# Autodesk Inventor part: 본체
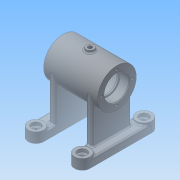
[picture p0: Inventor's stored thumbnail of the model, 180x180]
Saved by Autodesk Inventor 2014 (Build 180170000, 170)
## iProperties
Created: 2015-11
Part Number: 본체
Material: 알루미늄 6061
Document SubType Name: Modeling
Designer: net
Density: 2.71 g/cm^3
Appearance: 알루미늄 - 평지
Mass: 359.021 g
Surface Area: 459.454 cm^2
Volume: 132.48 cm^3
Author: net
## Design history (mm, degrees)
sketch "스케치1"
  geometry: C1 r 25 at (0, 0); 1 further point
  constraints: 1 centre point, 1 coincident
  dimensions: "d0" = 50 diameter of C1
extrude "돌출1" new body sketch "스케치1" distance "d1" = 70; taper "d2" = 0 deg
sketch "스케치2"
  geometry: C1 r 25 at (0, 0) reference; C2 r 16 at (0, 0)
  constraints: 1 centre point, 1 coincident
  dimensions: "d3" = 32 diameter of C2
extrude "돌출2" cut sketch "스케치2" distance "d4" = 12; taper "d5" = 0 deg
sketch "스케치3"
  geometry: C1 r 16 at (0, 0) reference; C2 r 14 at (0, 0)
  constraints: 1 centre point, 1 coincident
  dimensions: "d6" = 28 diameter of C2
extrude "돌출3" cut sketch "스케치3" distance "d7" = 2; taper "d8" = 0 deg
sketch "스케치4"
  geometry: C1 r 14 at (0, 0) reference; C2 r 21 at (0, 0)
  constraints: 1 centre point, 1 coincident
  dimensions: "d9" = 42 diameter of C2
extrude "돌출4" cut sketch "스케치4" distance "d10" = 42; taper "d11" = 0 deg
sketch "스케치5"
  geometry: C1 r 21 at (0, 0) reference; C2 r 14 at (0, 0)
  constraints: 1 centre point, 1 coincident
  dimensions: "d12" = 28 diameter of C2
extrude "돌출5" cut sketch "스케치5" distance "d13" = 2; taper "d14" = 0 deg
sketch "스케치6"
  geometry: C1 r 25 at (0, 0) reference; C2 r 16 at (0, 0)
  constraints: 1 centre point, 1 coincident
  dimensions: "d15" = 32 diameter of C2
extrude "돌출6" cut sketch "스케치6" distance "d16" = 12; taper "d17" = 0 deg
fillet "모깎기1" dims "d18" = 0.3
chamfer "모따기1" distance "d19" = 1; stored, may be unused: second distance "d20" = 2, angle "d21" = 45 deg
node "작업 평면2"
  node "작업 평면1"
sketch "스케치7"
  geometry: L1 (-25, 0)-(25, 0) reference; C1 r 5 at (0, 35); 1 further point
  constraints: 1 centre point
  dimensions: "d23" = 10 diameter of C1; "d24" = 35 distance from line of L1 C1.centre
extrude "돌출7" join sketch "스케치7" stored distance "d25" = 12; taper "d26" = 0 deg
fillet "모깎기2" dims "d27" = 2
sketch "스케치8"
  geometry: C1 r 5 at (0, 0) reference; 1 further point
hole "구멍1" sketch "스케치8" at (0, 0) diameter "d28" = 5.188; stored, may be unused: countersink angle "d32" = 90 deg, drill point angle "d34" = 118 deg; dims "d29" = 8, "d30" = 4, "d31" = 2, "d33" = 8
fillet "모깎기3" dims "d35" = 3
sketch "스케치9"
  geometry: C1 r 17 at (0, 0) reference; A1 r 20 centre (0, 0) between (0, 20) and (20, 0); 2 further points
  constraints: 4 point on circle, 1 centre point, 1 coincident
  dimensions: "d36" = 40 diameter of A1
hole "구멍2" sketch "스케치9" at (0, 20), (20, 0), (0, -20), (-20, 0) diameter "d37" = 3.242; stored, may be unused: countersink angle "d41" = 90 deg, drill point angle "d43" = 118 deg; dims "d38" = 8, "d39" = 4, "d40" = 2, "d42" = 10
sketch "스케치10"
  geometry: C1 r 17 at (0, 0) reference; A1 r 20 centre (0, 0) between (0, 20) and (20, 0); 2 further points
  constraints: 4 point on circle, 1 centre point, 1 coincident
  dimensions: "d44" = 40 diameter of A1
hole "구멍3" sketch "스케치10" at (0, 20), (20, 0), (0, -20), (-20, 0) diameter "d45" = 3.242; stored, may be unused: countersink angle "d49" = 90 deg, drill point angle "d51" = 118 deg; dims "d46" = 8, "d47" = 4, "d48" = 2, "d50" = 10
node "작업 평면4"
sketch "스케치11"
  geometry: L1 (0, 0)-(0, -25); L2 (0, 0)-(12.5, -21.651); L3 (12.5, -21.651)-(14, -24.249); L4 (14, -24.249)-(19.196, -21.249); L5 (19.196, -21.249)-(17.331, -18.018); A1 r 25 centre (0, 0) between (0, -25) and (12.5, -21.651) reference; 1 further point
  constraints: 10 end point, 3 point on circle, 2 perpendicular, 1 collinear, 1 vertical
  dimensions: "d53" = 30 deg angle of L2 L1; "d54" = 12 diameter of L4.end L3; "d55" = 28 distance from line of L4 point (0, 0)
revolve "회전1" sketch "스케치11" stored, may be unused: angle "d56" = 90 deg
sketch "스케치12"
  geometry: C1 r 6 at (0, 0) reference; 1 further point
hole "구멍4" sketch "스케치12" at (0, 0) diameter "d57" = 5.188; stored, may be unused: countersink angle "d61" = 90 deg, drill point angle "d63" = 118 deg; dims "d58" = 8, "d59" = 4, "d60" = 2, "d62" = 10
node "작업 평면5"
node "작업 평면6"
node "작업 평면7"
node "작업 평면8"
sketch "스케치15"
  geometry: L1 (-25, 0)-(-25, 70) reference; L2 (-25, 35)-(-17.013, 35); L3 (25, 70)-(-25, 70) reference; L4 (0, 70)-(0, 56.054); C1 r 10 at (40, 65); C2 r 10 at (-40, 65); 1 further point
  constraints: 4 end point, 2 centre point, 2 midpoint, 2 perpendicular, 1 symmetric about line, 1 other
  dimensions: "d81" = 20 diameter of C1; "d93" = 80 distance of C1.centre C2.centre; "d94" = 30 vertical distance of L2.end C2.centre
extrude "돌출10" join sketch "스케치15" distance "d89" = 13; taper "d90" = 0 deg
sketch "스케치16"
  geometry: L1 (-80, 10)-(0, 10); L2 (-80, -10)-(0, -10); A1 r 10 centre (0, 0) between (0, 10) and (0, -10) reference; A2 r 10 centre (-80, 0) between (-80, 10) and (-80, -10) reference; 1 further point
  constraints: 4 end point, 4 point on circle, 4 tangent
extrude "돌출11" join sketch "스케치16" distance "d91" = 10; taper "d92" = 0 deg
node "작업 평면9"
node "작업 평면12"
node "작업 평면14"
  node "작업 평면13"
sketch "스케치18"
  geometry: L1 (0, 10)-(80, 10) reference; L2 (15, 68)-(15, 10); L3 (65, 68)-(65, 10); A1 r 25 centre (40, 68) between (15, 68) and (65, 68) reference; 1 further point
  constraints: 4 end point, 2 perpendicular, 2 point on circle, 2 point on line, 2 tangent
extrude "돌출13" join sketch "스케치18" distance "d102" = 8; taper "d103" = 0 deg
node "작업 평면15"
fillet "모깎기7" dims "d105" = 2
fillet "모깎기10" dims "d111" = 2
fillet "모깎기14" dims "d115" = 2
fillet "모깎기17" dims "d127" = 2
sketch "스케치21"
  geometry: C1 r 10 at (0, 0) reference; C2 r 6 at (0, 0); 1 further point
  constraints: 1 centre point, 1 coincident
  dimensions: "d128" = 12 diameter of C2
extrude "돌출16" cut sketch "스케치21" distance "d129" = 4; taper "d130" = 0 deg
fillet "모깎기18" dims "d131" = 0.3
sketch "스케치22"
  geometry: C1 r 3 at (0, -10); A1 r 10 centre (0, -10) between (0, 0) and (0, -20) reference; 1 further point
  constraints: 1 centre point, 1 coincident
  dimensions: "d132" = 6 diameter of C1
extrude "돌출17" cut sketch "스케치22" stored distance "d133" = 4; taper "d134" = 0 deg
chamfer "모따기2" distance "d135" = 1; stored, may be unused: second distance "d136" = 2, angle "d137" = 45 deg
node "작업 평면16"
node "솔리드1"
mirror "대칭2"
mirror "대칭3"
mirror "대칭4"
mirror "대칭5"
mirror "대칭6"
other parameters: "d22" = 3, "d52" = 35, "d64" = 35, "d65" = -68, "d79" = 35, "d80" = -68, "d95" = 35, "d104" = 35, "d138" = 35
